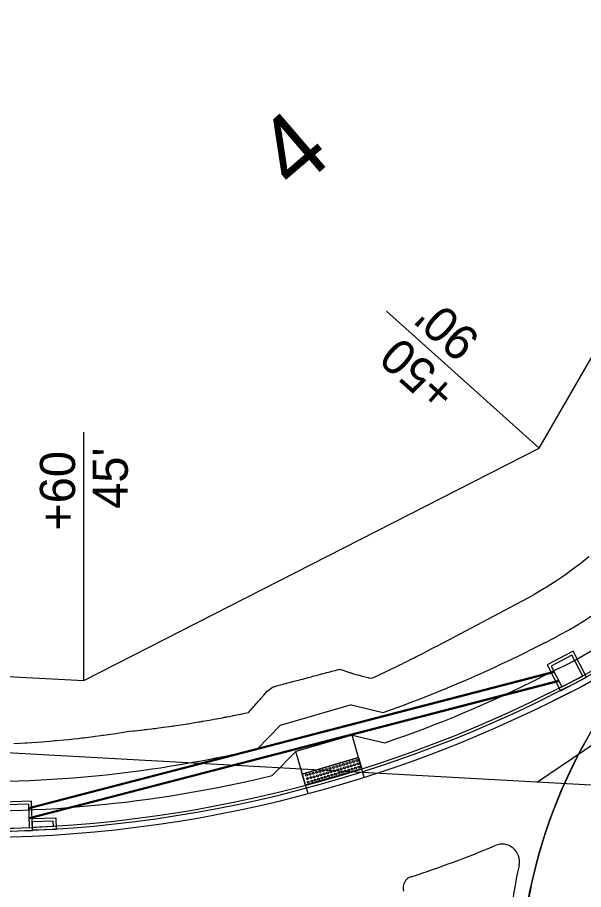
# Model space of a CAD drawing. Extents: x 670017 to 673226, y 705371 to 707498.
# Drawn here: x 671551.1 to 671647.7, y 706559.8 to 706708.6 of the extents above; entities that cross this region are included whole.
import ezdxf

# ---------------------------------------------------------------- set-up
doc = ezdxf.new("R2010")
doc.units = 0
for name, color, linetype in [('EL L 264', 7, 'Continuous'), ('EL L SCBV', 7, 'Continuous'), ('R_Drainage Stage 1A', 7, 'Continuous'), ('R_Horz Alg Station Annot', 7, 'Continuous'), ('R_No Plot', 7, 'Continuous'), ('R_No Plot FOC', 7, 'Continuous'), ('R_Proposed Const Limits Stage 1A', 7, 'Continuous'), ('R_Proposed Median', 7, 'Continuous'), ('R_Proposed Road Stage 1A', 7, 'Continuous'), ('R_Proposed Sidewalk Stage 1A', 7, 'Continuous'), ('R_ROW', 7, 'Continuous'), ('R_ROW Annot', 7, 'Continuous'), ('S_EXIST_ROW', 7, 'Continuous')]:
    doc.layers.add(name, color=color, linetype=linetype)

msp = doc.modelspace()

# ---------------------------------------------------------------- linework, layer by layer
at = {"layer": 'EL L 264'}
msp.add_line((671642.51, 706591.98), (671645.47, 706593.45), dxfattribs=at)
for centre, radius, start, end in [((671607.03, 706670.39), 86, 296.5471, 312.7972), ((671543.74, 706789.68), 221, 266.9958, 296.5471), ((671543.74, 706789.68), 221, 266.9958, 296.5471)]:
    msp.add_arc(centre, radius, start, end, dxfattribs=at)
at = {"layer": 'EL L SCBV'}
msp.add_arc((671726.73, 706541.35), 90, 132.9015, 220.6505, dxfattribs=at)
at = {"layer": 'R_Drainage Stage 1A'}
for p, q in [((671642.65, 706596.98), (671553.05, 706573.75)), ((671642.73, 706596.83), (671553.05, 706573.58)), ((671643.45, 706595.46), (671553.1, 706572.05)), ((671643.53, 706595.31), (671553.11, 706571.88))]:
    msp.add_line(p, q, dxfattribs=at)
for points in [[(671645.92, 706600.44), (671641.49, 706598.13), (671643.8, 706593.7), (671648.24, 706596.01)], [(671645.71, 706599.77), (671642.16, 706597.92), (671644.02, 706594.37), (671647.56, 706596.22)], [(671553.51, 706574.88), (671548.51, 706574.72), (671548.68, 706569.72), (671553.68, 706569.88)], [(671553.03, 706574.37), (671549.03, 706574.23), (671549.16, 706570.23), (671553.16, 706570.37)], [(671553.61, 706571.9), (671557.61, 706572.03), (671557.67, 706570.03), (671553.67, 706569.9)], [(671553.63, 706571.4), (671557.12, 706571.52), (671557.16, 706570.52), (671553.66, 706570.4)]]:
    msp.add_lwpolyline(points, close=True, dxfattribs=at)
at = {"layer": 'R_No Plot'}
msp.add_circle((671726.73, 706541.35), 90, dxfattribs=at)
at = {"layer": 'R_No Plot FOC'}
msp.add_line((671645.02, 706594.35), (671642.06, 706592.87), dxfattribs=at)
for centre, radius, start, end in [((671607.03, 706670.39), 85, 296.5471, 331.8875), ((671543.74, 706789.68), 220, 266.9958, 296.5471)]:
    msp.add_arc(centre, radius, start, end, dxfattribs=at)
at = {"layer": 'R_Proposed Const Limits Stage 1A'}
for points in [[(671648.63, 706616.57), (671647.29, 706615.49), (671645.89, 706614.44), (671645.39, 706614.07), (671644.44, 706613.39), (671642.92, 706612.36), (671641.33, 706611.35), (671640.88, 706611.07), (671639.65, 706610.34), (671639.09, 706610.02)], [(671611.59, 706595.86), (671612.71, 706596.38), (671613.37, 706596.69), (671613.39, 706596.7), (671613.57, 706596.79), (671614.27, 706597.11), (671614.66, 706597.3), (671614.74, 706597.34), (671614.82, 706597.38), (671615.82, 706597.86), (671615.9, 706597.9), (671616.26, 706598.08), (671616.77, 706598.32), (671617.13, 706598.5), (671617.68, 706598.77), (671618.05, 706598.96), (671618.4, 706599.14), (671618.78, 706599.33), (671619.08, 706599.48), (671620.26, 706600.08), (671620.78, 706600.35), (671621.72, 706600.84), (671622.47, 706601.23), (671622.55, 706601.27), (671622.77, 706601.39), (671639.09, 706610.02)], [(671590.55, 706590), (671591.33, 706590.89), (671591.47, 706591.05), (671591.83, 706591.46), (671592.2, 706591.88), (671592.5, 706592.22), (671592.65, 706592.39), (671593.14, 706592.95), (671593.54, 706593.4), (671593.78, 706593.68), (671593.81, 706593.71), (671594.62, 706594.33), (671594.98, 706594.42), (671595.07, 706594.45), (671595.11, 706594.46), (671596.01, 706594.71), (671596.24, 706594.77), (671596.5, 706594.84), (671596.57, 706594.86), (671596.89, 706594.94), (671597.22, 706595.03), (671597.88, 706595.21), (671597.89, 706595.21), (671598.15, 706595.29), (671598.34, 706595.34), (671598.57, 706595.4), (671599.26, 706595.58), (671599.37, 706595.61), (671599.73, 706595.71), (671600.38, 706595.88), (671600.64, 706595.95), (671600.67, 706595.96), (671600.79, 706595.99), (671601.21, 706596.1), (671601.31, 706596.13), (671601.47, 706596.17), (671601.53, 706596.19), (671602.01, 706596.31), (671602.05, 706596.32), (671602.88, 706596.54), (671602.88, 706596.54), (671602.95, 706596.56), (671603, 706596.57), (671603.38, 706596.67), (671603.69, 706596.75), (671603.72, 706596.76), (671603.88, 706596.8), (671604.44, 706596.95), (671604.56, 706596.98), (671604.74, 706597.03), (671605.34, 706597.18), (671605.85, 706597.31), (671606, 706597.35), (671606.1, 706597.37), (671607.74, 706596.84), (671607.88, 706596.79), (671608.04, 706596.74), (671608.44, 706596.61), (671609.37, 706596.36), (671609.4, 706596.35), (671609.75, 706596.26), (671610.88, 706595.97), (671610.98, 706595.95), (671611.05, 706595.93), (671611.59, 706595.86)], [(671550.49, 706584.7), (671552.47, 706584.81), (671552.69, 706584.82), (671555.22, 706584.99), (671555.24, 706585), (671557.16, 706585.15), (671557.51, 706585.19), (671557.78, 706585.21), (671559, 706585.33), (671559.8, 706585.41), (671560.31, 706585.46), (671560.7, 706585.5), (671561.41, 706585.58), (671562.07, 706585.66), (671562.39, 706585.7), (671562.82, 706585.75), (671564.09, 706585.91), (671564.34, 706585.94), (671565.32, 706586.07), (671565.63, 706586.11), (671565.78, 706586.13), (671566.6, 706586.25), (671567.48, 706586.38), (671567.81, 706586.43), (671568.85, 706586.59), (671569.17, 706586.64), (671569.83, 706586.75), (671570.29, 706586.81), (671570.86, 706586.87), (671571.1, 706586.89), (671572.57, 706587.05), (671572.77, 706587.08), (671573.09, 706587.11), (671573.35, 706587.15), (671574.05, 706587.23), (671574.27, 706587.26), (671574.56, 706587.29), (671575.24, 706587.38), (671575.6, 706587.42), (671575.97, 706587.47), (671576.04, 706587.48), (671577.52, 706587.69), (671577.67, 706587.71), (671577.71, 706587.71), (671577.84, 706587.73), (671578.26, 706587.79), (671579, 706587.9), (671579.36, 706587.96), (671580.08, 706588.07), (671580.17, 706588.08), (671580.49, 706588.13), (671581.06, 706588.23), (671581.97, 706588.38), (671582.3, 706588.43), (671582.48, 706588.46), (671582.61, 706588.49), (671582.74, 706588.51), (671583.46, 706588.63), (671584.43, 706588.81), (671584.52, 706588.83), (671584.94, 706588.9), (671585.05, 706588.92), (671586.11, 706589.11), (671586.43, 706589.17), (671586.69, 706589.22), (671586.74, 706589.23), (671587.3, 706589.34), (671587.48, 706589.38), (671587.78, 706589.43), (671587.81, 706589.44), (671587.91, 706589.46), (671588.84, 706589.65), (671588.95, 706589.67), (671589.39, 706589.76), (671589.45, 706589.77), (671589.9, 706589.87), (671590.55, 706590)]]:
    msp.add_lwpolyline(points, dxfattribs=at)
at = {"layer": 'R_Proposed Median'}
for centre, radius, start, end in [((671564.5, 706728.5), 175, 287.9015, 292.9029), ((671633.77, 706564.54), 3, 347.7048, 112.9029), ((671726.1, 706544.41), 91.5, 167.7048, 190.8442), ((671618.9, 706560.07), 2, 107.9015, 196.2292)]:
    msp.add_arc(centre, radius, start, end, dxfattribs=at)
at = {"layer": 'R_Proposed Road Stage 1A'}
for p, q in [((671644.8, 706594.8), (671641.84, 706593.32)), ((671645.47, 706593.45), (671642.51, 706591.98))]:
    msp.add_line(p, q, dxfattribs=at)
for centre, radius, start, end in [((671607.03, 706670.39), 84.5, 296.5471, 331.8875), ((671607.03, 706670.39), 86, 296.5471, 331.8875), ((671543.74, 706789.68), 221, 266.9958, 296.5471), ((671543.74, 706789.68), 219.5, 266.9958, 296.5471)]:
    msp.add_arc(centre, radius, start, end, dxfattribs=at)
at = {"layer": 'R_Proposed Sidewalk Stage 1A'}
for p, q in [((671641.22, 706601.95), (671638.27, 706600.47)), ((671643.46, 706597.48), (671640.5, 706596)), ((671608.06, 706591.3), (671595.93, 706587.77)), ((671608.06, 706591.3), (671613.52, 706590.02)), ((671595.93, 706587.77), (671592.01, 706583.76)), ((671608.19, 706586.14), (671598.59, 706583.34)), ((671610.29, 706578.93), (671608.19, 706586.14)), ((671608.19, 706586.14), (671613.78, 706584.82)), ((671598.59, 706583.34), (671594.58, 706579.23)), ((671600.69, 706576.14), (671598.59, 706583.34)), ((671609.31, 706582.29), (671599.71, 706579.5))]:
    msp.add_line(p, q, dxfattribs=at)
msp.add_lwpolyline([(671609.87, 706580.37), (671600.27, 706577.58), (671599.71, 706579.5), (671609.31, 706582.29)], close=True, dxfattribs=at)
for centre in [(671607.89, 706581.46), (671608.46, 706581.63), (671609.04, 706581.8), (671602.7, 706579.95), (671603.28, 706580.12), (671603.85, 706580.29), (671604.43, 706580.46), (671604.6, 706579.88), (671605.01, 706580.63), (671605.17, 706580.05), (671605.58, 706580.79), (671605.75, 706580.22), (671606.16, 706580.96), (671606.33, 706580.38), (671606.73, 706581.13), (671606.9, 706580.55), (671607.07, 706579.98), (671607.31, 706581.3), (671607.48, 706580.72), (671607.65, 706580.14), (671608.05, 706580.89), (671608.22, 706580.31), (671608.63, 706581.06), (671608.8, 706580.48), (671609.21, 706581.22), (671609.37, 706580.65), (671600.4, 706579.28), (671600.57, 706578.71), (671600.97, 706579.45), (671601.14, 706578.88), (671601.55, 706579.62), (671601.72, 706579.04), (671601.89, 706578.47), (671602.13, 706579.79), (671602.29, 706579.21), (671602.46, 706578.63), (671602.87, 706579.38), (671603.04, 706578.8), (671603.45, 706579.55), (671603.61, 706578.97), (671604.02, 706579.71), (671604.19, 706579.14), (671604.77, 706579.31), (671605.34, 706579.47), (671605.92, 706579.64), (671606.49, 706579.81), (671600.73, 706578.13), (671601.31, 706578.3)]:
    msp.add_circle(centre, 0.165, dxfattribs=at)
for centre, radius, start, end in [((671607.03, 706670.39), 76.5, 296.5471, 331.8875), ((671607.03, 706670.39), 81.5, 296.5471, 331.8875), ((671543.74, 706789.68), 211.5, 289.2645, 296.5471), ((671543.74, 706789.68), 216.5, 288.8766, 296.5471), ((671543.74, 706789.68), 211.5, 266.9958, 283.194), ((671543.74, 706789.68), 216.5, 266.9958, 283.5818)]:
    msp.add_arc(centre, radius, start, end, dxfattribs=at)
at = {"layer": 'R_ROW'}
msp.add_lwpolyline([(670753.27, 706632.89), (670820.8, 706679.41), (670885.98, 706681), (670933.29, 706628.45), (671562.42, 706595.43), (671640.16, 706635.12), (671682.63, 706708.58)], dxfattribs=at)
at = {"layer": 'R_ROW Annot'}
for points in [[(671640.16, 706635.12), (671628.99, 706645.13), (671614.1, 706658.48)], [(671562.42, 706595.43), (671562.42, 706617.85), (671562.42, 706637.85)]]:
    msp.add_lwpolyline(points, dxfattribs=at)
at = {"layer": 'S_EXIST_ROW'}
for points in [[(671639.86, 706578.18), (671678.12, 706604.07), (671682.63, 706708.58)], [(670020.59, 706668.53), (670619.99, 706639.58), (670619.86, 706634.58), (671728.16, 706573.3), (673225.88, 706490.48)]]:
    msp.add_lwpolyline(points, dxfattribs=at)

# ---------------------------------------------------------------- texts
at = {"layer": 'R_Horz Alg Station Annot'}
msp.add_text('4', height=12, rotation=40.6354, dxfattribs=at).set_placement((671598.42, 706678.58))
at = {"layer": 'R_ROW Annot'}
for s, rotation, p in [("90'", 138.1214, (671630.36, 706653.97)), ('+50', 138.1214, (671626.57, 706645.28)), ('+60', 90, (671560.92, 706621)), ("45'", 90, (671569.92, 706624.74))]:
    msp.add_text(s, height=6, rotation=rotation, dxfattribs=at).set_placement(p)

doc.saveas('drawing.dxf')
